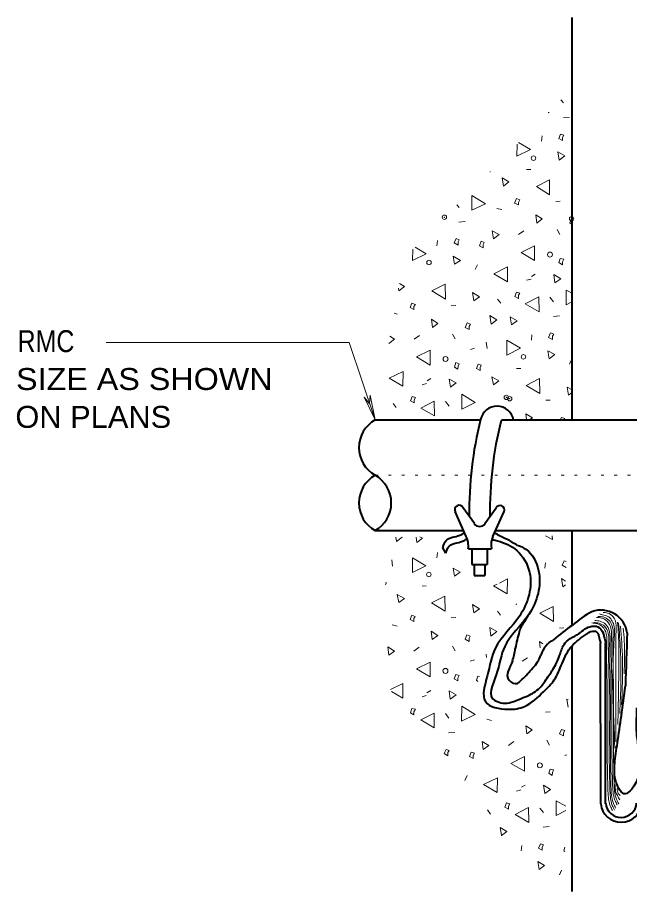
# Model space of a CAD drawing. Extents: x 312583 to 312854, y 144419 to 144597.
# Drawn here: x 312713.61 to 312734.8, y 144448.6 to 144478.87 of the extents above; entities that cross this region are included whole.
import ezdxf

# ---------------------------------------------------------------- set-up
doc = ezdxf.new("R2010")
doc.units = 0
doc.header["$LTSCALE"] = 0.3
doc.header["$PDMODE"] = 32
doc.header["$PDSIZE"] = 0.15
doc.linetypes.add('DOTTED', pattern=[1.5, 0.3, -1.2])
doc.layers.add('1', color=7, linetype='Continuous', lineweight=13)

msp = doc.modelspace()

# ---------------------------------------------------------------- linework, layer by layer
at = {"layer": '1', "lineweight": 40}
for p, q in [((312732.8052, 144464.9318), (312732.8052, 144478.8698)), ((312725.9896, 144464.9318), (312729.6312, 144464.9318)), ((312730.3596, 144464.9318), (312746.0532, 144464.9318)), ((312729.1406, 144460.8991), (312728.7572, 144461.7655)), ((312729.4242, 144461.3438), (312729.0256, 144461.8958)), ((312729.7922, 144461.3438), (312730.1832, 144461.8881)), ((312730.0606, 144460.8915), (312730.4516, 144461.7578)), ((312725.9896, 144461.0985), (312729.0486, 144461.0985)), ((312728.1976, 144461.0985), (312729.0486, 144461.0985)), ((312730.1602, 144461.0985), (312735.0976, 144461.0985)), ((312732.8052, 144457.8171), (312732.8052, 144461.0985)), ((312728.4352, 144460.3165), (312728.3356, 144460.5081)), ((312729.2172, 144460.4698), (312730.0146, 144460.4698)), ((312729.3399, 144460.4621), (312729.3399, 144459.9255)), ((312729.8689, 144460.4621), (312729.8689, 144459.9255)), ((312729.3399, 144459.9255), (312729.8689, 144459.9255)), ((312729.4166, 144459.9255), (312729.4166, 144459.5421)), ((312729.7922, 144459.9255), (312729.7922, 144459.5421)), ((312729.4166, 144459.5421), (312729.7922, 144459.5421)), ((312731.1722, 144457.9475), (312731.3102, 144458.2005)), ((312732.8052, 144448.6018), (312732.8052, 144457.1118)), ((312733.8019, 144451.6378), (312733.7942, 144457.2191)), ((312733.9706, 144451.6378), (312733.9629, 144457.2191))]:
    msp.add_line(p, q, dxfattribs=at)
at = {"layer": '1'}
for p, q in [((312732.4219, 144476.0178), (312732.5139, 144475.9105)), ((312731.9849, 144475.5808), (312732.0079, 144475.5655)), ((312732.0079, 144475.5655), (312732.0079, 144475.5961)), ((312732.5062, 144475.4045), (312732.7132, 144475.4198)), ((312731.7472, 144474.5841), (312731.7702, 144474.7681)), ((312731.2336, 144473.6028), (312731.3792, 144473.6028)), ((312732.2456, 144472.4988), (312732.3989, 144472.5065)), ((312728.8186, 144472.3761), (312728.8952, 144472.2918)), ((312730.1986, 144472.2535), (312730.3749, 144472.2151)), ((312728.3816, 144471.9468), (312728.3892, 144471.9545)), ((312728.8876, 144471.7858), (312729.1022, 144471.8011)), ((312731.1416, 144471.4791), (312730.9576, 144471.3488)), ((312732.2916, 144471.5251), (312732.3836, 144471.3565)), ((312728.1286, 144470.9655), (312728.1516, 144471.1495)), ((312729.5316, 144470.3061), (312729.4472, 144470.1375)), ((312731.2336, 144469.7695), (312731.3869, 144469.8078)), ((312731.4022, 144469.8998), (312731.5326, 144469.9765)), ((312726.8022, 144469.4935), (312726.8099, 144469.4091)), ((312732.0386, 144469.1791), (312732.1612, 144469.0258)), ((312732.8052, 144469.3171), (312732.6059, 144469.4321)), ((312728.6269, 144468.8801), (312728.7802, 144468.8955)), ((312730.2292, 144469.1178), (312730.3366, 144468.9721)), ((312726.6489, 144468.6271), (312726.7562, 144468.5965)), ((312732.1612, 144468.5198), (312732.3682, 144468.5351)), ((312727.5229, 144467.8605), (312727.3389, 144467.7301)), ((312728.6729, 144467.9065), (312728.7649, 144467.7378)), ((312731.4022, 144467.6995), (312731.4176, 144467.8835)), ((312729.2862, 144467.3775), (312729.4242, 144467.4235)), ((312729.8382, 144467.6228), (312729.8689, 144467.4081)), ((312732.7976, 144467.0325), (312732.7132, 144466.8638)), ((312730.8809, 144466.7181), (312731.0342, 144466.7181)), ((312727.6226, 144466.1508), (312727.7682, 144466.1891)), ((312727.7912, 144466.2888), (312727.9216, 144466.3655)), ((312732.6826, 144465.7905), (312732.8052, 144465.8825)), ((312725.6139, 144465.7215), (312725.7979, 144465.4915)), ((312725.9896, 144464.9318), (312725.6139, 144465.7215)), ((312725.8132, 144465.7905), (312725.7979, 144465.4915)), ((312725.9896, 144464.9318), (312725.8132, 144465.7905)), ((312728.4199, 144465.5681), (312728.5502, 144465.4071)), ((312730.6509, 144465.6678), (312730.5282, 144465.7138)), ((312731.9006, 144465.6141), (312732.0462, 144465.6218)), ((312726.6106, 144465.4991), (312726.7179, 144465.3611)), ((312726.7026, 144460.8685), (312726.7332, 144460.7228)), ((312727.4079, 144460.8761), (312727.4386, 144460.6921)), ((312731.8852, 144460.9221), (312732.1306, 144460.7918)), ((312732.1306, 144460.7918), (312732.1229, 144460.9221)), ((312726.5646, 144460.0865), (312726.5952, 144459.8718)), ((312728.1286, 144460.1631), (312728.1516, 144460.3471)), ((312731.8699, 144459.8028), (312731.8929, 144459.9868)), ((312727.6149, 144459.1818), (312727.7606, 144459.1895)), ((312732.4832, 144459.1588), (312732.5752, 144459.2278)), ((312730.2216, 144458.3155), (312730.3289, 144458.1698)), ((312730.8809, 144458.5608), (312730.8732, 144458.5301)), ((312728.6269, 144458.0778), (312728.7802, 144458.0931)), ((312726.5799, 144457.8401), (312726.7562, 144457.7941)), ((312732.3682, 144457.7175), (312732.5216, 144457.7328)), ((312727.5152, 144457.0581), (312727.3312, 144456.9278)), ((312728.6652, 144457.1041), (312728.7572, 144456.9355)), ((312729.8306, 144456.8205), (312729.8459, 144456.7055)), ((312729.2786, 144456.5828), (312729.4242, 144456.6211)), ((312731.2642, 144456.6978), (312731.0802, 144456.5751)), ((312727.7836, 144455.4865), (312727.9139, 144455.5631)), ((312726.5569, 144455.5325), (312726.9479, 144455.2948)), ((312727.6149, 144455.3485), (312727.7606, 144455.3868)), ((312732.6672, 144455.2488), (312732.6289, 144455.2641)), ((312728.4199, 144454.7658), (312728.5426, 144454.6048)), ((312731.8929, 144454.8118), (312732.0462, 144454.8195)), ((312729.8536, 144454.5665), (312730.0222, 144454.5281)), ((312728.5349, 144454.0988), (312728.7496, 144454.1141)), ((312730.7889, 144453.7921), (312730.6049, 144453.6618)), ((312731.9389, 144453.8381), (312732.0309, 144453.6695)), ((312732.5522, 144453.3091), (312732.6289, 144453.3321)), ((312729.1789, 144452.6191), (312729.0946, 144452.4505)), ((312731.0572, 144452.2128), (312731.1799, 144452.2895)), ((312730.8886, 144452.0825), (312731.0342, 144452.1208)), ((312732.5906, 144451.5535), (312732.2609, 144451.7451)), ((312729.8766, 144451.4308), (312729.9839, 144451.2851)), ((312731.6859, 144451.4921), (312731.8162, 144451.3388)), ((312731.8086, 144450.8328), (312732.0156, 144450.8481)), ((312731.0496, 144450.0125), (312731.0726, 144450.1965)), ((312732.4449, 144449.3455), (312732.3682, 144449.1768))]:
    msp.add_line(p, q, dxfattribs=at)
at = {"layer": '1', "linetype": 'DOTTED'}
msp.add_line((312725.9896, 144463.0151), (312767.7882, 144463.0151), dxfattribs=at)
at = {"layer": '1'}
for points in [[(312732.4756, 144474.7145), (312732.5216, 144474.7911), (312732.4066, 144474.8295), (312732.3452, 144474.6761), (312732.4756, 144474.6071)], [(312732.3606, 144473.9325), (312732.5522, 144474.0781), (312732.3146, 144474.2161)], [(312730.4286, 144473.0278), (312730.6202, 144473.1735), (312730.3826, 144473.3115)], [(312732.0309, 144472.7288), (312732.0309, 144473.2501), (312731.5709, 144473.0125)], [(312729.3399, 144472.7058), (312729.3322, 144472.1921), (312729.8076, 144472.4221)], [(312730.9499, 144472.4681), (312730.9959, 144472.5525), (312730.8809, 144472.5985), (312730.8196, 144472.4375), (312730.9499, 144472.3761)], [(312731.5862, 144471.7475), (312731.7779, 144471.8931), (312731.5479, 144472.0311)], [(312730.0836, 144471.2031), (312730.2829, 144471.3488), (312730.0452, 144471.4868)], [(312728.8646, 144471.1035), (312728.9029, 144471.1725), (312728.7956, 144471.2108), (312728.7266, 144471.0651), (312728.8646, 144470.9885)], [(312729.7309, 144471.0038), (312729.7692, 144471.0805), (312729.6619, 144471.1188), (312729.6082, 144470.9655), (312729.7309, 144470.8965)], [(312731.5096, 144470.4518), (312731.5096, 144470.9655), (312731.0419, 144470.7278)], [(312728.7419, 144470.3215), (312728.9412, 144470.4595), (312728.6959, 144470.6051)], [(312732.4756, 144470.4135), (312732.5216, 144470.4978), (312732.3989, 144470.5285), (312732.3452, 144470.3828), (312732.4756, 144470.3061)], [(312730.5666, 144469.7158), (312730.5666, 144470.2295), (312730.0989, 144469.9918)], [(312732.2149, 144469.6775), (312732.4142, 144469.8231), (312732.1766, 144469.9688)], [(312728.4199, 144469.1178), (312728.4122, 144469.6315), (312727.9522, 144469.4015)], [(312729.4089, 144469.0565), (312729.6082, 144469.1945), (312729.3629, 144469.3401)], [(312730.9576, 144469.2481), (312731.0036, 144469.3248), (312730.8809, 144469.3631), (312730.8272, 144469.2098), (312730.9576, 144469.1408)], [(312731.6629, 144468.6808), (312731.6552, 144469.1945), (312731.1876, 144468.9568)], [(312727.3312, 144468.8571), (312727.3849, 144468.9338), (312727.2622, 144468.9798), (312727.2009, 144468.8265), (312727.3312, 144468.7575)], [(312727.9752, 144468.1288), (312728.1592, 144468.2745), (312727.9369, 144468.4201)], [(312729.2402, 144468.1748), (312729.2862, 144468.2515), (312729.1712, 144468.2898), (312729.1099, 144468.1365), (312729.2402, 144468.0675)], [(312730.0069, 144468.2515), (312730.1986, 144468.4048), (312729.9609, 144468.5505)], [(312730.7122, 144468.2208), (312730.9039, 144468.3665), (312730.6662, 144468.5045)], [(312730.5512, 144467.6995), (312730.5512, 144467.1781), (312731.0189, 144467.4158)], [(312732.1306, 144467.8298), (312732.1766, 144467.9065), (312732.0616, 144467.9448), (312731.9926, 144467.7915), (312732.1306, 144467.7225)], [(312727.8909, 144466.8331), (312727.8986, 144467.3468), (312727.4232, 144467.1168)], [(312732.0156, 144467.0478), (312732.2072, 144467.1935), (312731.9696, 144467.3315)], [(312728.8646, 144466.7948), (312728.9029, 144466.8791), (312728.7879, 144466.9175), (312728.7342, 144466.7641), (312728.8569, 144466.6951)], [(312729.6236, 144466.7488), (312729.6619, 144466.8255), (312729.5546, 144466.8638), (312729.4932, 144466.7181), (312729.6236, 144466.6415)], [(312726.9479, 144466.0971), (312726.9556, 144466.6108), (312726.4802, 144466.3808)], [(312728.5962, 144466.0665), (312728.7956, 144466.2121), (312728.5579, 144466.3501)], [(312730.0836, 144466.1431), (312730.2752, 144466.2888), (312730.0299, 144466.4268)], [(312731.6859, 144465.8441), (312731.6782, 144466.3655), (312731.2182, 144466.1278)], [(312727.3389, 144465.6295), (312727.3849, 144465.7138), (312727.2699, 144465.7445), (312727.2162, 144465.5911), (312727.3389, 144465.5221)], [(312728.0442, 144465.0698), (312728.0366, 144465.5835), (312727.5689, 144465.3458)], [(312728.9949, 144465.8211), (312728.9872, 144465.3075), (312729.4549, 144465.5375)], [(312727.2776, 144460.1631), (312727.2776, 144459.6495), (312727.7452, 144459.8795)], [(312728.7419, 144459.5191), (312728.9336, 144459.6571), (312728.6959, 144459.8028)], [(312726.8099, 144458.6068), (312727.0016, 144458.7525), (312726.7562, 144458.8905)], [(312728.4122, 144458.3155), (312728.4046, 144458.8291), (312727.9446, 144458.5991)], [(312729.4089, 144458.2541), (312729.6006, 144458.3921), (312729.3629, 144458.5378)], [(312732.1612, 144457.9551), (312732.1536, 144458.4688), (312731.6936, 144458.2388)], [(312727.3312, 144458.0548), (312727.3772, 144458.1315), (312727.2622, 144458.1775), (312727.2009, 144458.0241), (312727.3312, 144457.9551)], [(312729.9992, 144457.4491), (312730.1986, 144457.6025), (312729.9609, 144457.7481)], [(312727.9676, 144457.3265), (312728.1592, 144457.4721), (312727.9292, 144457.6178)], [(312729.2402, 144457.3725), (312729.2786, 144457.4491), (312729.1636, 144457.4875), (312729.1099, 144457.3418), (312729.2402, 144457.2651)], [(312726.4649, 144456.7821), (312726.6642, 144456.9278), (312726.4266, 144457.0735)], [(312727.8909, 144456.0308), (312727.8909, 144456.5445), (312727.4232, 144456.3145)], [(312728.8569, 144455.9925), (312728.9029, 144456.0768), (312728.7802, 144456.1151), (312728.7266, 144455.9618), (312728.8492, 144455.8928)], [(312728.5886, 144455.2641), (312728.7956, 144455.4098), (312728.5579, 144455.5478)], [(312727.3312, 144454.8271), (312727.3849, 144454.9115), (312727.2622, 144454.9421), (312727.2086, 144454.7888), (312727.3312, 144454.7198)], [(312728.9872, 144455.0188), (312728.9796, 144454.5051), (312729.4549, 144454.7351)], [(312728.0366, 144454.2675), (312728.0366, 144454.7811), (312727.5689, 144454.5435)], [(312731.2412, 144454.0605), (312731.4252, 144454.2061), (312731.2029, 144454.3441)], [(312732.5062, 144454.0988), (312732.5522, 144454.1755), (312732.4372, 144454.2138), (312732.3759, 144454.0681), (312732.5062, 144453.9915)], [(312729.7309, 144453.5161), (312729.9302, 144453.6618), (312729.6926, 144453.7998)], [(312728.5119, 144453.4165), (312728.5579, 144453.4855), (312728.4429, 144453.5238), (312728.3739, 144453.3781), (312728.5119, 144453.3015)], [(312729.3782, 144453.3168), (312729.4242, 144453.3935), (312729.3092, 144453.4318), (312729.2556, 144453.2785), (312729.3782, 144453.2095)], [(312731.1569, 144452.7648), (312731.1646, 144453.2785), (312730.6892, 144453.0408)], [(312732.1306, 144452.7265), (312732.1689, 144452.8108), (312732.0539, 144452.8415), (312732.0002, 144452.6958), (312732.1229, 144452.6191)], [(312730.2139, 144452.0288), (312730.2216, 144452.5425), (312729.7462, 144452.3048)], [(312731.8622, 144451.9905), (312732.0616, 144452.1361), (312731.8239, 144452.2818)], [(312730.6049, 144451.5611), (312730.6509, 144451.6378), (312730.5359, 144451.6761), (312730.4822, 144451.5228), (312730.6049, 144451.4538)], [(312731.3102, 144450.9938), (312731.3026, 144451.5075), (312730.8349, 144451.2698)], [(312731.7779, 144450.1428), (312731.8239, 144450.2195), (312731.7089, 144450.2578), (312731.6476, 144450.1045), (312731.7779, 144450.0355)], [(312731.6629, 144449.3608), (312731.8546, 144449.5065), (312731.6169, 144449.6445)]]:
    msp.add_lwpolyline(points, close=True, dxfattribs=at)
for points in [[(312730.9039, 144474.4845), (312730.8962, 144474.0628), (312731.3639, 144474.3005), (312730.9576, 144474.5458)], [(312729.9609, 144473.5261), (312729.9686, 144473.5261), (312729.9686, 144473.5415)], [(312732.7899, 144471.9008), (312732.7286, 144471.7551), (312732.7899, 144471.7091)], [(312727.2929, 144470.8428), (312727.2776, 144470.4518), (312727.7529, 144470.6818), (312727.3696, 144470.9195)], [(312726.8099, 144469.4091), (312727.0016, 144469.5548), (312726.8329, 144469.6545)], [(312732.6059, 144469.4321), (312732.6059, 144468.9185), (312732.7976, 144469.0181)], [(312726.4649, 144467.5845), (312726.6642, 144467.7301), (312726.5032, 144467.8298)], [(312716.6746, 144467.6151), (312725.0849, 144467.6151), (312725.9896, 144464.9318)], [(312732.8052, 144465.9745), (312732.6366, 144466.0665), (312732.6826, 144465.7905)], [(312731.3256, 144464.9395), (312731.4329, 144465.0085), (312731.2029, 144465.1465), (312731.2336, 144464.9395)], [(312732.5216, 144464.9395), (312732.5522, 144464.9778), (312732.4372, 144465.0161), (312732.3989, 144464.9395)], [(312726.7332, 144460.7228), (312726.9249, 144460.8761), (312726.9172, 144460.8761)], [(312727.4386, 144460.6921), (312727.6302, 144460.8378), (312727.5382, 144460.8838)], [(312732.6059, 144460.0251), (312732.5292, 144460.0481), (312732.4679, 144459.9025)], [(312732.4679, 144459.9025), (312732.5982, 144459.8258), (312732.6059, 144459.8258)], [(312726.3499, 144459.2278), (312726.3882, 144459.2968), (312726.3499, 144459.2968)], [(312730.2139, 144459.2431), (312730.0912, 144459.1895), (312730.5589, 144458.9135)], [(312730.5589, 144458.9135), (312730.5666, 144459.4271), (312730.2982, 144459.2815)], [(312732.5829, 144459.3505), (312732.4372, 144459.4425), (312732.4832, 144459.1588)], [(312731.8009, 144457.1808), (312731.6782, 144457.2575), (312731.7012, 144457.0428)], [(312729.6006, 144456.0461), (312729.5469, 144456.0615), (312729.4932, 144455.9158), (312729.5469, 144455.8775)], [(312726.9479, 144455.2948), (312726.9479, 144455.8085), (312726.5186, 144455.5938)], [(312732.6289, 144455.2641), (312732.6596, 144455.0418), (312732.6749, 144454.9881)], [(312732.2609, 144451.7451), (312732.2532, 144451.2315), (312732.5906, 144451.4078)], [(312730.3596, 144450.5338), (312730.3672, 144450.5415), (312730.5512, 144450.6795), (312730.3136, 144450.8175)], [(312730.3136, 144450.8175), (312730.3596, 144450.5491), (312730.3596, 144450.5338)], [(312732.5599, 144450.1351), (312732.5216, 144450.0125), (312732.5599, 144449.9895)]]:
    msp.add_lwpolyline(points, dxfattribs=at)
for centre, radius in [((312731.4707, 144474.0003), 0.0783), ((312732.0433, 144470.6586), 0.0865), ((312727.8548, 144470.3844), 0.0783), ((312728.4274, 144467.0427), 0.0865), ((312731.1238, 144467.1155), 0.0783), ((312727.8506, 144459.5823), 0.0783), ((312728.4232, 144456.2406), 0.0865), ((312731.6921, 144452.9716), 0.0865)]:
    msp.add_circle(centre, radius, dxfattribs=at)
at = {"layer": '1', "lineweight": 40}
for centre, radius, start, end in [((312730.2085, 144464.8246), 0.5827, 10.59906, 167.86288), ((312726.5294, 144463.9735), 1.0999, 119.39202, 240.60798), ((312742.2831, 144461.7755), 13.0359, 165.91883, 180.82259), ((312742.9961, 144461.7449), 13.0359, 165.91883, 180.72864), ((312726.5294, 144462.0568), 1.0999, 119.39202, 240.60798), ((312725.4497, 144462.0568), 1.0999, 299.39202, 60.60798), ((312728.8952, 144461.8268), 0.151, 27.89727, 203.96249), ((312730.3136, 144461.8191), 0.151, 336.03751, 152.10273), ((312729.6082, 144461.4743), 0.23, 215.31121, 324.68879), ((312728.3739, 144460.5541), 0.8438, 354.28941, 24.22774), ((312730.8502, 144460.5925), 0.8438, 159.26129, 188.35075), ((312735.1106, 144455.2416), 3.4521, 117.90046, 131.55753), ((312733.8073, 144457.4319), 0.9154, 7.82046, 109.93461), ((312731.7578, 144457.3964), 0.8041, 136.73863, 165.15216), ((312736.2219, 144452.7716), 6.0913, 123.94503, 131.71155), ((312738.5616, 144455.4993), 7.8673, 164.49454, 168.85639), ((313422.463, 144433.6184), 688.1652, 178.00654, 178.15919), ((312732.5877, 144456.5154), 0.906, 117.53092, 162.36962), ((312729.2899, 144457.1441), 1.5576, 338.88002, 355.42457), ((312730.7122, 144457.1099), 1.0614, 313.90004, 342.44507), ((312739.6043, 144452.7162), 9.6682, 156.42656, 158.68794), ((312730.8569, 144456.0946), 0.2929, 152.43739, 282.29595), ((312729.1732, 144458.1126), 2.881, 311.24609, 322.15663), ((312730.4439, 144456.4908), 0.8316, 304.86219, 319.11223), ((312734.5072, 144451.7068), 0.7073, 185.66371, 355.10091), ((312734.5072, 144451.7068), 0.5386, 185.66371, 355.10091)]:
    msp.add_arc(centre, radius, start, end, dxfattribs=at)
for points in [[(312728.3356, 144460.5081), (312728.4506, 144460.7611), (312728.9182, 144460.9375), (312729.0792, 144461.0218)], [(312730.9116, 144460.6001), (312730.7429, 144460.6845), (312730.6356, 144460.7535), (312730.3596, 144460.8838), (312730.1756, 144460.9835), (312730.1142, 144461.0065)], [(312728.4352, 144460.3165), (312728.5426, 144460.5541), (312729.0102, 144460.7305), (312729.1712, 144460.8148)], [(312730.0606, 144460.7841), (312730.2216, 144460.7458), (312730.8962, 144460.4085), (312731.3332, 144459.6571), (312730.9959, 144458.1545), (312730.1602, 144457.0428), (312729.8689, 144456.0615), (312729.8076, 144455.1798), (312730.5972, 144454.9115), (312731.1646, 144455.0111), (312731.8162, 144455.5171), (312732.1919, 144455.9311), (312732.4602, 144456.4985), (312732.7976, 144457.1041), (312733.3112, 144457.5105)], [(312730.9116, 144460.6001), (312731.2106, 144460.4545), (312731.6476, 144459.7031), (312731.3102, 144458.2005), (312730.4746, 144457.0888), (312730.1832, 144456.1075), (312730.1219, 144455.2258), (312730.1602, 144455.2105)], [(312730.1602, 144455.2105), (312730.4056, 144455.1261), (312730.7046, 144455.1568), (312731.0419, 144455.2871), (312731.3179, 144455.4021), (312731.7319, 144455.7011), (312731.8622, 144455.8775), (312732.1459, 144456.2915), (312732.3759, 144456.7745), (312732.5292, 144457.1578), (312732.7439, 144457.3648), (312733.0506, 144457.5335), (312733.2499, 144457.6945), (312733.4876, 144457.7865), (312733.7022, 144457.7711), (312733.8786, 144457.5565), (312733.9092, 144457.4568), (312733.9552, 144457.2881), (312733.9629, 144457.2191)], [(312733.3112, 144457.5105), (312733.4109, 144457.5871), (312733.4722, 144457.6101), (312733.5719, 144457.6178), (312733.6256, 144457.6178), (312733.6792, 144457.5718), (312733.7176, 144457.5181), (312733.7329, 144457.4338), (312733.7559, 144457.3418), (312733.7789, 144457.2575), (312733.7942, 144457.2191)], [(312735.0439, 144454.9651), (312735.0286, 144454.3748), (312735.0439, 144454.0068), (312734.8752, 144452.1515), (312734.6452, 144451.9828), (312734.3386, 144452.3815), (312734.2849, 144453.0408), (312734.3769, 144453.7385), (312734.5149, 144454.6891), (312734.6529, 144455.7241)]]:
    msp.add_spline(points, degree=3, dxfattribs=at)
at = {"layer": '1'}
for points in [[(312734.3232, 144453.7845), (312734.3309, 144457.6791), (312734.3079, 144457.9628), (312734.2312, 144458.1161), (312734.0319, 144458.2465), (312733.8786, 144458.2695)], [(312733.5949, 144457.9858), (312733.7789, 144457.9628), (312733.9706, 144457.8555), (312734.1009, 144457.6101), (312734.1162, 144457.1808), (312734.1162, 144456.4448), (312734.1316, 144455.5325), (312734.1316, 144453.7461), (312734.1546, 144452.2435), (312734.2389, 144451.6531), (312734.3156, 144451.4921)], [(312733.6486, 144458.0931), (312733.8326, 144458.0701), (312734.0242, 144457.9628), (312734.1546, 144457.7175), (312734.1699, 144457.2881), (312734.1699, 144456.5521), (312734.1852, 144455.6398), (312734.1852, 144453.8535), (312734.2082, 144452.3508), (312734.2926, 144451.7605), (312734.3692, 144451.5995)], [(312733.7022, 144458.1315), (312733.8862, 144458.1085), (312734.0779, 144458.0011), (312734.2082, 144457.7558), (312734.2236, 144457.3265), (312734.2236, 144456.5905), (312734.2389, 144455.6781), (312734.2389, 144453.8918), (312734.2619, 144452.3891), (312734.3462, 144451.7988), (312734.4229, 144451.6378)], [(312733.7559, 144458.2158), (312733.8556, 144458.1851), (312734.0472, 144458.1315), (312734.1469, 144458.0395), (312734.2389, 144457.8785), (312734.2696, 144457.3955), (312734.2926, 144453.5621)], [(312733.4876, 144457.9015), (312733.6716, 144457.8785), (312733.8632, 144457.7711), (312733.9936, 144457.5258), (312734.0089, 144457.0965), (312734.0089, 144456.3605), (312734.0242, 144455.4481), (312734.0242, 144453.6618), (312734.0472, 144452.1591), (312734.1316, 144451.5688), (312734.2082, 144451.4078)], [(312733.5566, 144457.9168), (312733.7406, 144457.8938), (312733.9322, 144457.7865), (312734.0626, 144457.5411), (312734.0779, 144457.1118), (312734.0779, 144456.3758), (312734.0932, 144455.4635), (312734.0932, 144453.6771), (312734.1162, 144452.1745), (312734.2006, 144451.5841), (312734.2772, 144451.4231)], [(312734.3846, 144457.9321), (312734.4306, 144457.0351), (312734.4306, 144456.6825), (312734.3922, 144454.3901)], [(312734.4152, 144457.9091), (312734.4842, 144456.9661), (312734.4612, 144454.7658)], [(312734.5226, 144455.0648), (312734.5532, 144456.6595), (312734.4842, 144457.7865)], [(312734.5762, 144457.7251), (312734.6146, 144457.2881), (312734.6069, 144456.1381)], [(312734.3002, 144452.3048), (312734.3156, 144452.0748), (312734.4612, 144451.7758)], [(312734.3692, 144452.1668), (312734.4076, 144451.9981), (312734.4766, 144451.9215)]]:
    msp.add_spline(points, degree=3, dxfattribs=at)
for p in [(312728.3892, 144471.9545), (312732.7899, 144471.9008), (312730.5282, 144465.7138), (312730.6509, 144465.6678)]:
    msp.add_point(p, dxfattribs=at)

# ---------------------------------------------------------------- texts
for s, width, p in [('RMC', 0.85, (312713.6096, 144467.2807)), ('SIZE AS SHOWN', 1.1, (312713.556, 144465.9697)), ('ON PLANS', 1.05, (312713.533, 144464.6587))]:
    msp.add_text(s, height=0.76, dxfattribs=dict(at, width=width)).set_placement(p)

doc.saveas('drawing.dxf')
